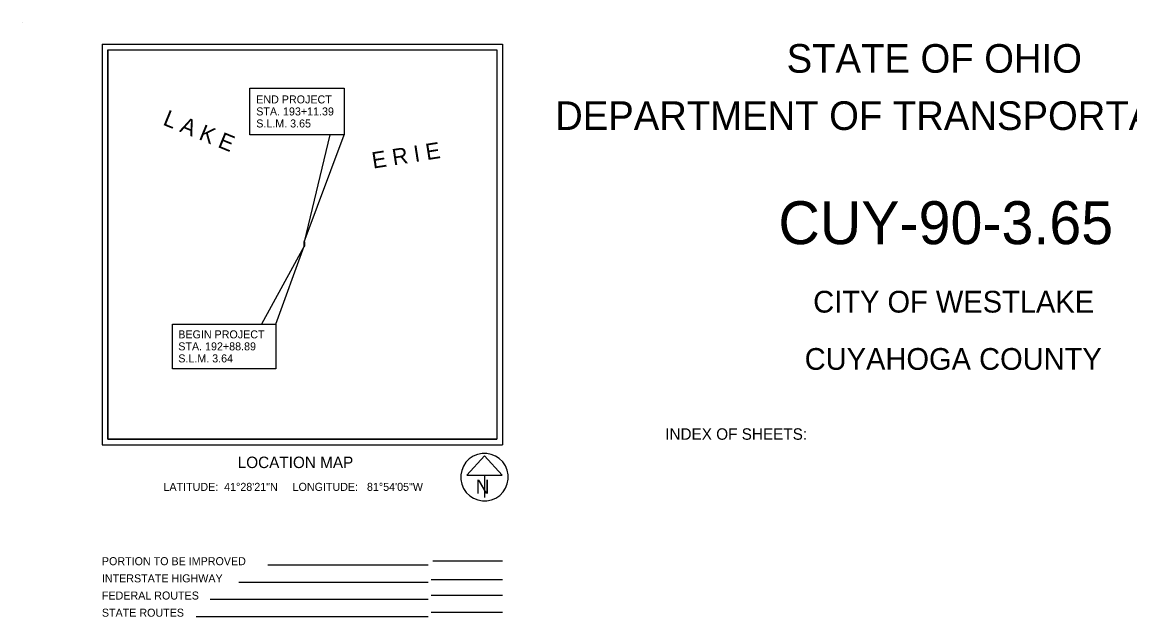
# Model space of a CAD drawing. Extents: x 2080852 to 2433556, y 1080825 to 1306626.
# Drawn here: x 2080852 to 2285387, y 1196937 to 1306626 of the extents above; entities that cross this region are included whole.
import ezdxf

# ---------------------------------------------------------------- set-up
doc = ezdxf.new("R2010")
doc.units = 0
for name, color, linetype in [('Default', 7, 'Continuous'), ('PM_P_Chevron_Line', 7, 'Continuous'), ('PM_P_Dotted_Line', 7, 'Continuous'), ('PM_P_Lane_Line', 7, 'Continuous'), ('SC_Scratch1', 7, 'Continuous'), ('UT_X_Gas', 7, 'Continuous'), ('XS_P_Pavt_Surface', 7, 'Continuous')]:
    doc.layers.add(name, color=color, linetype=linetype)

msp = doc.modelspace()

# ---------------------------------------------------------------- linework, layer by layer
at = {"layer": 'PM_P_Dotted_Line'}
for points in [[(2122883, 1294440), (2140290, 1294440), (2140290, 1285863), (2122883, 1285863)], [(2108588, 1250928), (2127717, 1250928), (2127717, 1242651), (2108588, 1242651)]]:
    msp.add_lwpolyline(points, close=True, dxfattribs=at)
at = {"layer": 'PM_P_Lane_Line'}
for p, q in [((2095636, 1302585), (2169556, 1302585)), ((2095636, 1302585), (2095636, 1228665)), ((2096692, 1301529), (2096692, 1229721)), ((2096692, 1301529), (2168500, 1301529)), ((2168500, 1301529), (2168500, 1229721)), ((2169556, 1302585), (2169556, 1228665)), ((2096692, 1229721), (2168500, 1229721)), ((2095636, 1228665), (2169556, 1228665)), ((2166225, 1226648), (2162977, 1223045)), ((2169473, 1223045), (2166225, 1226648)), ((2162977, 1223045), (2169473, 1223045)), ((2166225, 1223045), (2166225, 1218961)), ((2166225, 1222702), (2166225, 1222702)), ((2166225, 1222702), (2166225, 1222702)), ((2156701, 1207293), (2169556, 1207293)), ((2155828, 1206462), (2126193, 1206462)), ((2155828, 1203294), (2120870, 1203294)), ((2169556, 1203760), (2156356, 1203760)), ((2169556, 1200891), (2156356, 1200891)), ((2155828, 1200126), (2115546, 1200126)), ((2155828, 1196958), (2113005, 1196958)), ((2169556, 1197723), (2156356, 1197723))]:
    msp.add_line(p, q, dxfattribs=at)
for points in [[(2140290, 1285863), (2137650, 1285863), (2132952, 1266120)], [(2132862, 1266121), (2132850, 1265308), (2133029, 1265305), (2133042, 1266119)], [(2125077, 1250928), (2127717, 1250928), (2132940, 1265306)]]:
    msp.add_lwpolyline(points, close=True, dxfattribs=at)
msp.add_arc((2166225, 1222702), 4380, 129.77984, 129.76332, dxfattribs=at)
at = {"layer": 'SC_Scratch1'}
msp.add_line((2080852, 1306626), (2080852, 1306626), dxfattribs=at)
at = {"layer": 'UT_X_Gas'}
msp.add_lwpolyline([(2096692, 1301529), (2168500, 1301529), (2168500, 1229721), (2096692, 1229721)], close=True, dxfattribs=at)

# ---------------------------------------------------------------- texts
at = {"layer": 'Default'}
for s, height, p in [('STATE OF OHIO', 5280, (2222018, 1297305)), ('DEPARTMENT OF TRANSPORTATION', 5280, (2179267, 1286745)), ('CUY-90-3.65', 7920, (2220497, 1265677)), ('CITY OF WESTLAKE', 4012.8, (2226918, 1253058)), ('CUYAHOGA COUNTY', 4012.8, (2225347, 1242498))]:
    msp.add_text(s, height=height, dxfattribs=at).set_placement(p)
at = {"layer": 'PM_P_Chevron_Line'}
for s, p in [('END PROJECT', (2124076, 1291640)), ('STA. 193+11.39', (2124076, 1289422)), ('S.L.M. 3.65', (2124076, 1287205)), ('BEGIN PROJECT', (2109683, 1248300)), ('STA. 192+88.89', (2109683, 1246083)), ('S.L.M. 3.64', (2109683, 1243865))]:
    msp.add_text(s, height=1478.4, dxfattribs=at).set_placement(p)
at = {"layer": 'PM_P_Lane_Line'}
for s, height, p in [('INDEX OF SHEETS:', 2112, (2199593, 1229599)), ('LOCATION MAP', 2112, (2120654, 1224375)), ('LATITUDE:  41°28\'21"N     LONGITUDE:   81°54\'05"W', 1478.4, (2106946, 1220173)), ('N', 2640, (2164584, 1219625)), ('PORTION TO BE IMPROVED', 1478.4, (2095577, 1206462)), ('INTERSTATE HIGHWAY', 1478.4, (2095577, 1203294)), ('FEDERAL ROUTES', 1478.4, (2095577, 1200126)), ('STATE ROUTES', 1478.4, (2095577, 1196958))]:
    msp.add_text(s, height=height, dxfattribs=at).set_placement(p)
at = {"layer": 'XS_P_Pavt_Surface'}
for s, rotation, p in [('L A K E', 337.88363, (2106677, 1287755)), ('E R I E', 8.94988, (2145669, 1279608))]:
    msp.add_text(s, height=3001.9, rotation=rotation, dxfattribs=at).set_placement(p)

doc.saveas('drawing.dxf')
